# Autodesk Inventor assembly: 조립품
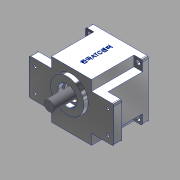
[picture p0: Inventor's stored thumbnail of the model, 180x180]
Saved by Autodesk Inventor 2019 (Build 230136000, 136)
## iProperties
Created: 2020-01
Part Number: 조립품
Material: 일반
Document SubType Name: Assembly
Designer: 323-3
Author: 323-3
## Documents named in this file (8)
- C:\Users\323-3\Desktop\700119V1002\조립품.iam
- C:\Users\323-3\Desktop\700119V1002\본체.ipt
- C:\Users\323-3\Desktop\700119V1002\커버.ipt
- C:\Users\323-3\Desktop\700119V1002\메인 축.ipt
- C:\Users\323-3\Desktop\700119V1002\서브 축.ipt
- C:\Users\323-3\Desktop\700119V1002\볼트 M4.ipt
- C:\Users\323-3\Desktop\700119V1002\베어링 6003.ipt
- C:\Users\323-3\Desktop\700119V1002\베어링 608.ipt
